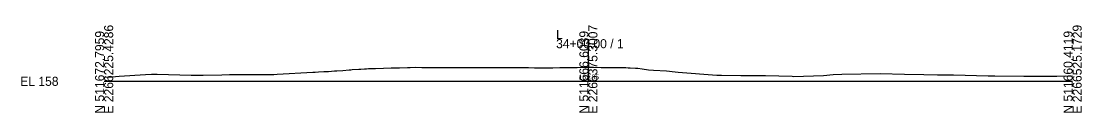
# Model space of a CAD drawing. Extents: x -827 to 2303, y -169 to 9934.
# Drawn here: x 1974.3 to 2302.8, y 2990.3 to 3017.3 of the extents above; entities that cross this region are included whole.
import ezdxf

# ---------------------------------------------------------------- set-up
doc = ezdxf.new("R2010")
doc.units = 0
for name, color, linetype in [('Default', 7, 'Continuous'), ('Exist Cross Section Cell', 7, 'Continuous'), ('Exist XS Center Line Elevation Label', 7, 'Continuous'), ('Exist XS Ground Line', 7, 'Continuous')]:
    doc.layers.add(name, color=color, linetype=linetype)

msp = doc.modelspace()

# ---------------------------------------------------------------- linework, layer by layer
at = {"layer": 'Exist Cross Section Cell'}
for p, q in [((2150, 3000), (2150, 3013.05)), ((2000, 3000), (2150, 3000)), ((2150, 3000), (2300, 3000))]:
    msp.add_line(p, q, dxfattribs=at)
at = {"layer": 'Exist XS Ground Line'}
msp.add_lwpolyline([(2000, 3001.28), (2002.36, 3001.44), (2004.65, 3001.57), (2012.8, 3002.13), (2014.66, 3002.21), (2016.38, 3002.21), (2026.98, 3001.93), (2030.68, 3001.95), (2036.46, 3002.05), (2038.83, 3002.06), (2043.39, 3002.09), (2050.43, 3002.14), (2052.56, 3002.16), (2053.55, 3002.2), (2064.6, 3002.79), (2065.41, 3002.84), (2066.35, 3002.91), (2068.09, 3003.02), (2068.87, 3003.06), (2069.52, 3003.08), (2071.37, 3003.21), (2072.08, 3003.27), (2073.91, 3003.37), (2075.89, 3003.53), (2076.37, 3003.57), (2076.84, 3003.61), (2078.87, 3003.76), (2079.47, 3003.8), (2080.65, 3003.87), (2081.22, 3003.9), (2081.92, 3003.93), (2082.74, 3003.96), (2083.55, 3003.99), (2084.1, 3004.01), (2086.49, 3004.06), (2088.9, 3004.18), (2091.53, 3004.22), (2093.99, 3004.3), (2094.83, 3004.32), (2096.39, 3004.33), (2098.44, 3004.32), (2098.87, 3004.32), (2100.86, 3004.32), (2101.38, 3004.32), (2101.95, 3004.32), (2103.87, 3004.29), (2104.54, 3004.29), (2106.39, 3004.28), (2106.82, 3004.28), (2107.44, 3004.28), (2108.18, 3004.27), (2108.89, 3004.26), (2109.79, 3004.27), (2111.4, 3004.28), (2112.85, 3004.29), (2113.89, 3004.29), (2115.29, 3004.3), (2116.39, 3004.3), (2117.67, 3004.29), (2118.89, 3004.29), (2120.08, 3004.29), (2121.47, 3004.29), (2122.56, 3004.29), (2123.9, 3004.28), (2125.48, 3004.27), (2126.44, 3004.26), (2128.07, 3004.26), (2128.94, 3004.25), (2130.68, 3004.24), (2131.43, 3004.23), (2133.29, 3004.2), (2133.94, 3004.19), (2134.53, 3004.17), (2136.41, 3004.14), (2137.93, 3004.16), (2138.95, 3004.18), (2141.13, 3004.23), (2141.45, 3004.23), (2143.95, 3004.28), (2146.53, 3004.31), (2148.93, 3004.34), (2150.06, 3004.35), (2151.54, 3004.33), (2153.91, 3004.31), (2156.1, 3004.3), (2156.41, 3004.29), (2158.52, 3004.26), (2158.93, 3004.26), (2159.37, 3004.26), (2161.56, 3004.24), (2162.34, 3004.22), (2162.92, 3004.17), (2164.6, 3004.06), (2165.36, 3004.02), (2166.65, 3003.86), (2168.64, 3003.56), (2170.12, 3003.47), (2174.16, 3003.23), (2176.87, 3002.96), (2177.82, 3002.84), (2189.76, 3001.94), (2191.25, 3001.87), (2197.24, 3001.83), (2198.96, 3001.84), (2204.85, 3001.79), (2213.17, 3001.57), (2213.58, 3001.52), (2222.83, 3001.77), (2225.81, 3002.13), (2228.55, 3002.21), (2240.43, 3002.47), (2247.96, 3002.19), (2253.89, 3002.1), (2258.17, 3002.04), (2263.06, 3001.97), (2273.83, 3001.67), (2274.92, 3001.66), (2275.92, 3001.65), (2284.93, 3001.6), (2285.53, 3001.61), (2295.15, 3001.59), (2300, 3001.66)], dxfattribs=at)

# ---------------------------------------------------------------- texts
at = {"layer": 'Default'}
msp.add_text('-', height=0.0001, dxfattribs=at).set_placement((2000, 3000))
msp.add_text('-', height=0.0001, dxfattribs=at).set_placement((2000, 3000))
at = {"layer": 'Exist Cross Section Cell'}
for s, p in [('E 2266225.4286', (2002.8, 2990)), ('E 2266375.3007', (2152.8, 2990)), ('E 2266525.1729', (2302.8, 2990)), ('N 511672.7959', (2000, 2990)), ('N 511666.6039', (2150, 2990)), ('N 511660.4119', (2300, 2990))]:
    msp.add_text(s, height=2.8, rotation=90, dxfattribs=at).set_placement(p)
for s, p in [('34+00.00 / 1', (2140, 3010.25)), ('L', (2140, 3013.05)), ('EL 158', (1974, 2998.6))]:
    msp.add_text(s, height=2.8, dxfattribs=at).set_placement(p)
at = {"layer": 'Exist XS Center Line Elevation Label'}
msp.add_text('162.35', height=1.5, dxfattribs=at).set_placement((2146.97, 3000.6))

doc.saveas('drawing.dxf')
